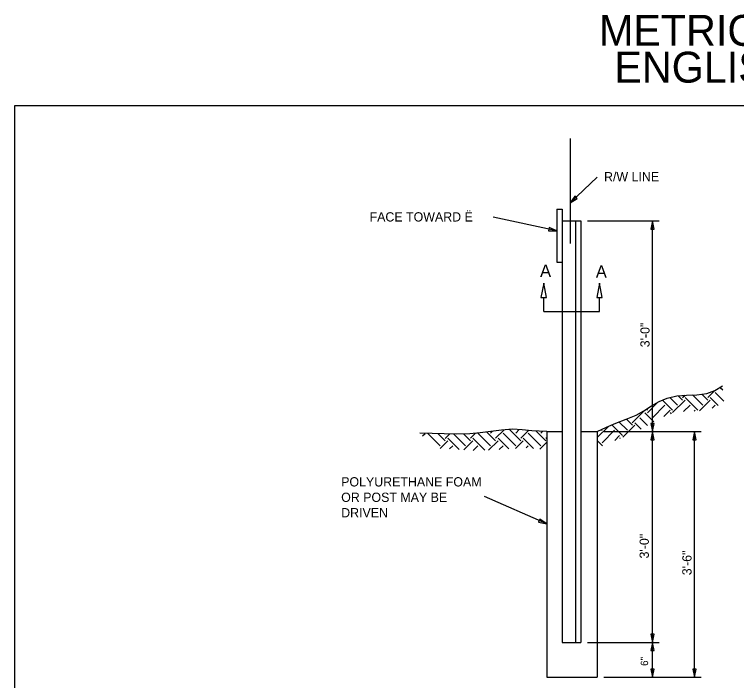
# Model space of a CAD drawing. Extents: x -439.1 to -392.2, y -458.1 to -436.2.
# Drawn here: x -439.11 to -427.41, y -446.98 to -436.2 of the extents above; entities that cross this region are included whole.
import ezdxf

# ---------------------------------------------------------------- set-up
doc = ezdxf.new("R2010")
doc.units = 0
for name, color, linetype in [('Bridge-Named Boundary', 7, 'Continuous'), ('Level 4', 7, 'Continuous'), ('Level 45', 7, 'Continuous'), ('Level 46', 7, 'Continuous')]:
    doc.layers.add(name, color=color, linetype=linetype)

msp = doc.modelspace()

# ---------------------------------------------------------------- linework, layer by layer
at = {"layer": 'Bridge-Named Boundary'}
msp.add_lwpolyline([(-439.109, -458.051), (-407.859, -458.051), (-407.859, -437.676), (-439.109, -437.676)], close=True, dxfattribs=at)
at = {"layer": 'Level 4'}
for p, q in [((-430.111, -438.205), (-430.111, -439.904)), ((-430.111, -439.248), (-429.67, -438.834)), ((-430.014, -439.157), (-430.111, -439.248)), ((-430.111, -439.248), (-430.014, -439.157)), ((-430.325, -439.351), (-430.325, -440.207)), ((-430.325, -439.351), (-430.237, -439.351)), ((-430.237, -439.351), (-430.237, -446.364)), ((-430.325, -439.703), (-431.357, -439.477)), ((-430.237, -439.539), (-429.934, -439.539)), ((-430.023, -439.539), (-430.023, -446.364)), ((-429.934, -439.539), (-429.934, -446.364)), ((-429.83, -439.539), (-428.668, -439.539)), ((-428.776, -442.952), (-428.776, -439.539)), ((-430.325, -440.207), (-430.237, -440.207)), ((-430.537, -441.007), (-430.537, -440.778)), ((-429.635, -441.007), (-429.635, -440.778)), ((-430.537, -441.007), (-429.635, -441.007)), ((-427.881, -442.4), (-427.765, -442.284)), ((-427.678, -442.237), (-427.637, -442.278)), ((-428.493, -442.4), (-428.369, -442.524)), ((-428.359, -442.372), (-428.288, -442.442)), ((-428.288, -442.401), (-428.248, -442.362)), ((-428.245, -442.4), (-428.041, -442.604)), ((-428.125, -442.357), (-427.96, -442.523)), ((-427.974, -442.345), (-427.878, -442.441)), ((-427.841, -442.4), (-427.712, -442.529)), ((-427.759, -442.319), (-427.62, -442.458)), ((-428.858, -442.646), (-428.694, -442.482)), ((-428.777, -442.728), (-428.573, -442.524)), ((-428.613, -442.443), (-428.451, -442.605)), ((-428.452, -442.645), (-428.248, -442.441)), ((-428.272, -442.628), (-428.167, -442.523)), ((-428.015, -442.615), (-427.84, -442.441)), ((-427.808, -442.572), (-427.759, -442.523)), ((-429.103, -442.809), (-428.901, -442.607)), ((-428.899, -442.646), (-428.754, -442.792)), ((-428.872, -442.589), (-428.856, -442.605)), ((-428.593, -442.706), (-428.491, -442.605)), ((-428.49, -442.645), (-428.472, -442.662)), ((-428.1, -442.619), (-428.085, -442.604)), ((-429.198, -442.752), (-429.1, -442.85)), ((-428.981, -442.727), (-428.854, -442.854)), ((-429.67, -443.049), (-429.483, -442.863)), ((-429.434, -442.842), (-429.263, -443.013)), ((-429.318, -442.795), (-429.182, -442.931)), ((-429.255, -443.043), (-429.062, -442.85)), ((-429.062, -442.809), (-428.956, -442.915)), ((-432.499, -443.022), (-432.457, -442.98)), ((-432.414, -442.981), (-432.212, -443.183)), ((-432.246, -442.987), (-432.131, -443.102)), ((-432.131, -443.061), (-432.061, -442.991)), ((-431.993, -442.993), (-431.803, -443.182)), ((-431.831, -442.991), (-431.721, -443.1)), ((-431.724, -443.06), (-431.646, -442.981)), ((-431.602, -442.978), (-431.398, -443.182)), ((-431.457, -442.96), (-431.317, -443.101)), ((-431.398, -442.978), (-431.367, -442.947)), ((-431.317, -443.06), (-431.18, -442.923)), ((-431.193, -442.977), (-430.989, -443.181)), ((-431.089, -442.917), (-430.907, -443.099)), ((-430.991, -442.977), (-430.935, -442.92)), ((-430.91, -443.059), (-430.784, -442.933)), ((-430.788, -442.977), (-430.584, -443.181)), ((-430.659, -442.943), (-430.502, -443.1)), ((-430.584, -442.977), (-430.555, -442.949)), ((-430.489, -442.951), (-430.489, -446.93)), ((-430.489, -442.951), (-430.237, -442.951)), ((-429.934, -442.951), (-429.67, -442.951)), ((-429.67, -442.951), (-429.67, -446.93)), ((-429.604, -442.919), (-429.591, -442.932)), ((-429.592, -443.135), (-429.388, -442.931)), ((-429.565, -442.952), (-427.988, -442.952)), ((-429.565, -442.952), (-428.668, -442.952)), ((-429.565, -442.952), (-428.668, -442.952)), ((-429.387, -443.094), (-429.307, -443.013)), ((-428.776, -446.364), (-428.776, -442.952)), ((-428.096, -446.93), (-428.096, -442.952)), ((-432.214, -443.223), (-432.091, -443.1)), ((-432.088, -443.059), (-431.904, -443.244)), ((-431.832, -443.249), (-431.683, -443.1)), ((-431.684, -443.06), (-431.488, -443.255)), ((-431.429, -443.251), (-431.277, -443.099)), ((-431.274, -443.058), (-431.101, -443.232)), ((-430.995, -443.226), (-430.869, -443.099)), ((-430.869, -443.059), (-430.703, -443.225)), ((-430.598, -443.234), (-430.489, -443.124)), ((-430.502, -443.059), (-430.489, -443.045)), ((-429.67, -443.096), (-429.583, -443.183)), ((-429.307, -443.054), (-429.301, -443.06)), ((-432.061, -443.233), (-432.01, -443.182)), ((-431.679, -443.259), (-431.602, -443.182)), ((-431.256, -443.241), (-431.195, -443.181)), ((-430.822, -443.215), (-430.787, -443.181)), ((-430.489, -444.447), (-431.495, -444)), ((-430.237, -446.364), (-429.934, -446.364)), ((-429.83, -446.364), (-428.681, -446.364)), ((-429.83, -446.364), (-428.668, -446.364)), ((-428.776, -446.93), (-428.776, -446.364)), ((-430.489, -446.93), (-429.67, -446.93)), ((-429.565, -446.93), (-427.988, -446.93)), ((-429.565, -446.93), (-428.681, -446.93))]:
    msp.add_line(p, q, dxfattribs=at)
for points in [[(-430.033, -439.137), (-430.111, -439.248), (-429.995, -439.177)], [(-428.749, -439.672), (-428.776, -439.539), (-428.804, -439.672)], [(-430.461, -439.701), (-430.325, -439.703), (-430.449, -439.648)], [(-430.461, -439.701), (-430.325, -439.703), (-430.449, -439.648)], [(-430.581, -440.783), (-430.493, -440.783), (-430.537, -440.549)], [(-429.678, -440.783), (-429.591, -440.783), (-429.635, -440.549)], [(-428.804, -442.819), (-428.776, -442.952), (-428.749, -442.819)], [(-428.749, -443.084), (-428.776, -442.952), (-428.804, -443.084)], [(-428.069, -443.084), (-428.096, -442.952), (-428.124, -443.084)], [(-430.621, -444.418), (-430.489, -444.447), (-430.599, -444.368)], [(-430.621, -444.418), (-430.489, -444.447), (-430.599, -444.368)], [(-428.804, -446.231), (-428.776, -446.364), (-428.749, -446.231)], [(-428.749, -446.496), (-428.776, -446.364), (-428.804, -446.496)], [(-428.804, -446.797), (-428.776, -446.93), (-428.749, -446.797)], [(-428.124, -446.797), (-428.096, -446.93), (-428.069, -446.797)]]:
    msp.add_lwpolyline(points, close=True, dxfattribs=at)
for points in [[(-430.014, -439.157), (-430.033, -439.137), (-430.111, -439.248)], [(-429.995, -439.177), (-430.014, -439.157)], [(-430.111, -439.248), (-429.995, -439.177)], [(-429.67, -442.952), (-429.521, -442.879), (-429.368, -442.813), (-429.203, -442.753), (-429.041, -442.687), (-428.913, -442.615), (-428.789, -442.536), (-428.666, -442.466), (-428.537, -442.41), (-428.382, -442.374), (-428.222, -442.36), (-428.057, -442.356), (-427.895, -442.335), (-427.764, -442.284), (-427.643, -442.209)], [(-430.489, -442.952), (-430.608, -442.947), (-430.728, -442.939), (-430.885, -442.923), (-431.043, -442.914), (-431.219, -442.926), (-431.395, -442.952), (-431.565, -442.974), (-431.735, -442.989), (-431.943, -442.994), (-432.151, -442.989), (-432.346, -442.984), (-432.541, -442.977)]]:
    msp.add_lwpolyline(points, dxfattribs=at)

# ---------------------------------------------------------------- texts
for s, height, p in [('R/W LINE', 0.15, (-429.56, -438.9)), ('FACE TOWARD Ë', 0.15, (-433.357, -439.55)), ('A', 0.2, (-430.596, -440.447)), ('A', 0.2, (-429.693, -440.46)), ('POLYURETHANE FOAM', 0.15, (-433.817, -443.84)), ('OR POST MAY BE', 0.15, (-433.817, -444.09)), ('DRIVEN', 0.15, (-433.817, -444.34))]:
    msp.add_text(s, height=height, dxfattribs=at).set_placement(p)
at = {"layer": 'Level 45'}
msp.add_text('ENGLISH - LEVEL 45 - RED', height=0.5, dxfattribs=at).set_placement((-429.393, -437.301))
for s, height, p in [('3\'-0"', 0.15, (-428.822, -441.587)), ('3\'-0"', 0.15, (-428.834, -445.006)), ('3\'-6"', 0.15, (-428.143, -445.277)), ('6"', 0.12, (-428.846, -446.746))]:
    msp.add_text(s, height=height, rotation=90, dxfattribs=at).set_placement(p)
at = {"layer": 'Level 46'}
msp.add_text('METRIC - LEVEL 46 - GREEN', height=0.5, dxfattribs=at).set_placement((-429.642, -436.705))

doc.saveas('drawing.dxf')
